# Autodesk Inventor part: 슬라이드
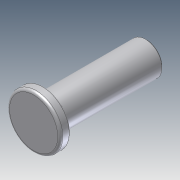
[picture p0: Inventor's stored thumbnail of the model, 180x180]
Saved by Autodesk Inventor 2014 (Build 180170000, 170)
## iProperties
Company: 한국ATC센터
Created: 2014-01
Part Number: 슬라이드
Document SubType Name: Modeling
Designer: KYOUNG IL JANG
Density: 1 g/cm^3
Material: 일반
Mass: 6.80356 g
Surface Area: 25.6477 cm^2
Volume: 6.80356 cm^3
Vendor: CBT Solutions
Appearance: 기본값
Author: KYOUNG IL JANG
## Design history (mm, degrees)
sketch "스케치1"
  geometry: L1 (13.5, 41)-(13.5, 74) reference; L2 (13.5, 74)-(26.5, 74) reference; L3 (20, 74)-(20, 29); L4 (20, 74)-(13.5, 74); L5 (13.5, 74)-(13.5, 33); L6 (13.5, 33)-(9.5, 33); L7 (9.5, 33)-(9.5, 29); L8 (20, 73.5)-(13.5, 73.5); L9 (20, 29)-(9.5, 29); 1 further point
  constraints: 16 end point, 4 perpendicular, 3 point on line, 1 collinear, 1 midpoint, 1 parallel, 1 vertical, 2 other
  dimensions: "d0" = 45 distance of L3.start L3.end; "d1" = 21 diameter of L7 L3; "d2" = 4 distance from line of L3.end L6; "d4" = 0.5 distance between parallel lines of L8 L2
revolve "회전1" sketch "스케치1" stored, may be unused: angle "d5" = 90 deg
fillet "모깎기1" dims "d6" = 1
fillet "모깎기3" dims "d8" = 0.5
chamfer "모따기1" distance "d9" = 0.5; stored, may be unused: second distance "d10" = 2, angle "d11" = 45 deg
sketch "스케치2"
  geometry: C1 r 6.5 at (0, 0) reference; C2 r 7.25 at (0, 0); 1 further point
  constraints: 1 centre point, 1 coincident
  dimensions: "d12" = 14.5 diameter of C2
extrude "돌출1" join sketch "스케치2" distance "d13" = 2; taper "d14" = 0 deg
node "솔리드1"
node "참조1"
